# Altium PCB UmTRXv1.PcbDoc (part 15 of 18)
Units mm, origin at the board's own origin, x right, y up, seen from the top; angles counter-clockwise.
Board outline 172 x 113 mm, 6 copper layers (Top Layer, GND, MidLayer1, Mid-Layer 2, InternalPlane2, Bottom Layer); 766 components, 613 nets, 3008 pads, 1360 vias.
Unrouted connection lines stored in the file: 2.
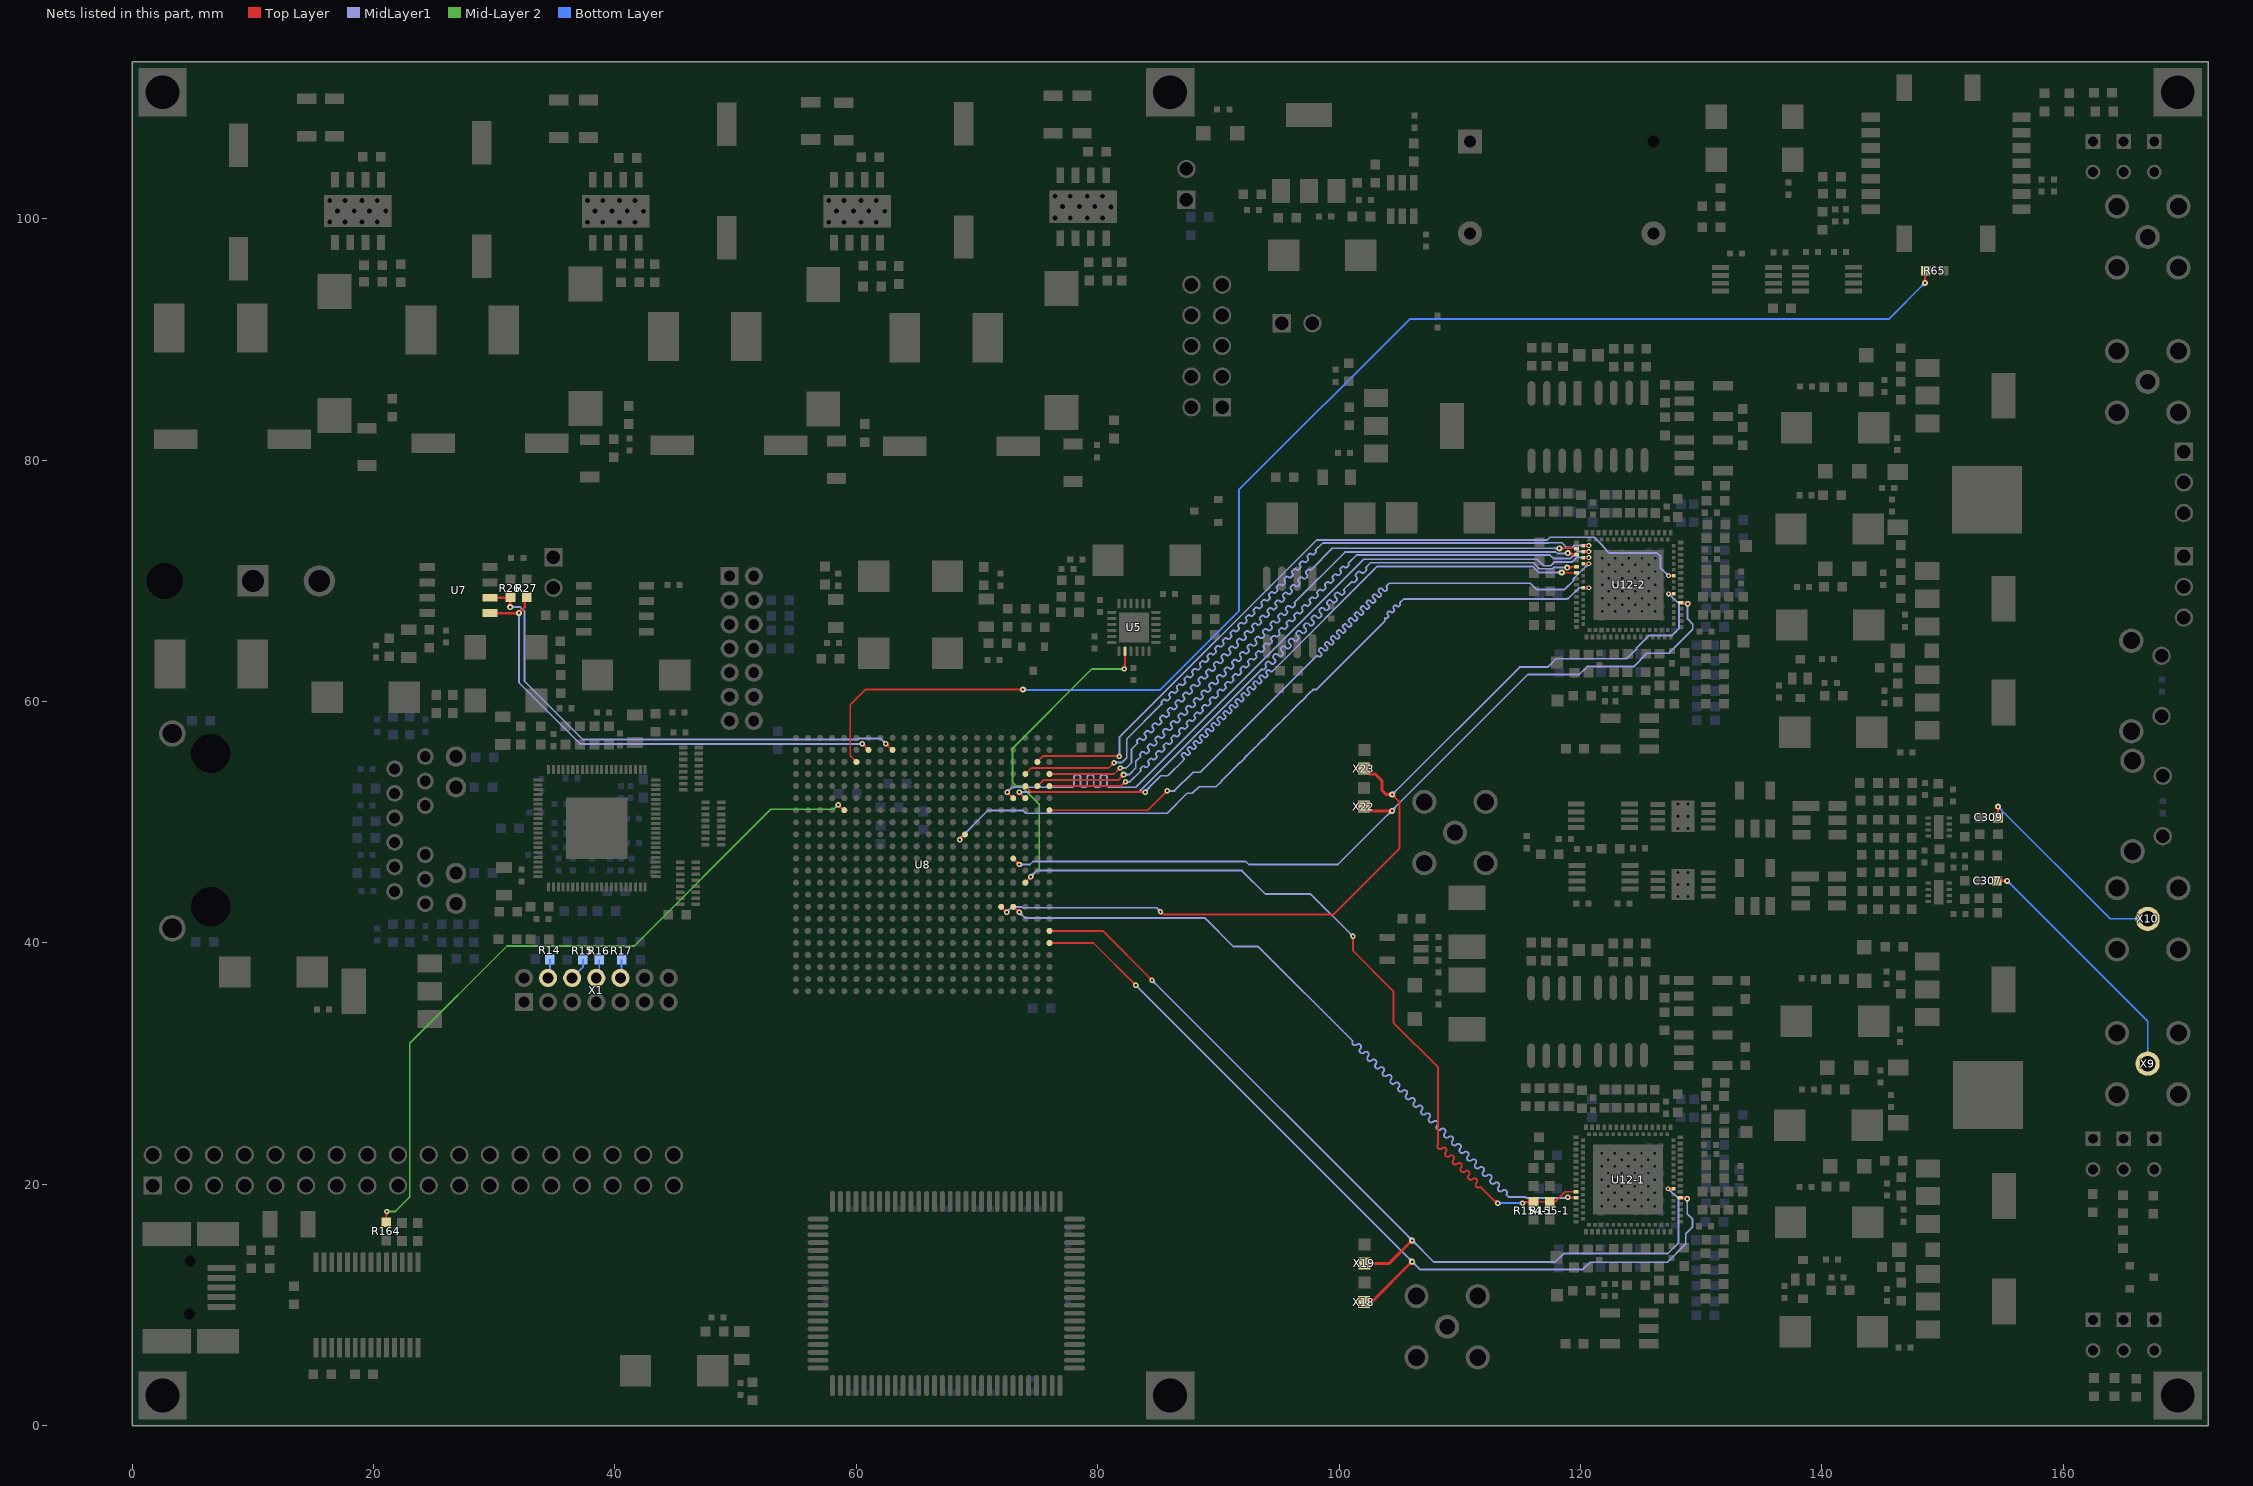
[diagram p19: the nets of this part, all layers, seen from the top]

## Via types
v1: diameter 0.45, hole 0.2, Top Layer to Bottom Layer, tented both sides, 554 vias
v2: diameter 0.5, hole 0.2, Top Layer to Bottom Layer, tented both sides, 468 vias
v3: diameter 0.7, hole 0.3, Top Layer to Bottom Layer, tented both sides, 206 vias
v4: diameter 0.4, hole 0.2, Top Layer to Bottom Layer, tented both sides, 82 vias
v5: diameter 0.8, hole 0.3, Top Layer to Bottom Layer, tented both sides, 16 vias
v6: diameter 0.6, hole 0.25, Top Layer to Bottom Layer, tented both sides, 16 vias
v7: diameter 0.5, hole 0.3, Top Layer to Bottom Layer, tented both sides, 8 vias
v8: diameter 0.7, hole 0.3, Top Layer to Bottom Layer, 4 vias
v9: diameter 0.6, hole 0.3, Top Layer to Bottom Layer, tented both sides, 4 vias
v10: diameter 0.5, hole 0.2, Top Layer to Bottom Layer, 2 vias

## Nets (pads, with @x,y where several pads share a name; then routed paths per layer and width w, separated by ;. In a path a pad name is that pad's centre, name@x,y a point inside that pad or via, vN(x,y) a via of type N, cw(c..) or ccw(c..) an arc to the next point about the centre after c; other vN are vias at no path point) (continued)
RX2D4: U8.V3 U12-2.11 | length 65.1
  Top Layer w0.15: U8.V3@74,53 74.5,52.5 v1(83.95,52.5) ; v1@83.844,52.394 ccw(c83.588,52.138) 83.588,52.5 ccw(c83.588,52.862) v1@83.844,52.606 ; v2(118.45,70.7) 118.475,70.675 119.666,70.675 U12-2.11@119.671,70.68
  MidLayer1 w0.15: v1(83.95,52.5) 83.95,52.566 85.234,53.85 85.8,53.85 87.105,55.155 ccw(c87.006,55.254) 87.105,55.353 86.991,55.467 cw(c87.09,55.566) 86.991,55.665 87.041,55.715 cw(c87.14,55.616) 87.239,55.715 87.353,55.601 ccw(c87.452,55.7) 87.551,55.601 87.6,55.65 ccw(c87.501,55.749) 87.6,55.848 87.486,55.962 cw(c87.585,56.061) 87.486,56.16 87.536,56.21 cw(c87.635,56.111) 87.734,56.21 87.848,56.096 ccw(c87.947,56.195) 88.046,56.096 88.095,56.145 ccw(c87.996,56.244) 88.095,56.343 87.981,56.457 cw(c88.08,56.556) 87.981,56.655 88.031,56.705 cw(c88.13,56.606) 88.229,56.705 88.343,56.591 ccw(c88.442,56.69) 88.541,56.591 88.59,56.64 ccw(c88.491,56.739) 88.59,56.838 88.476,56.952 cw(c88.575,57.051) 88.476,57.15 88.526,57.2 cw(c88.625,57.101) 88.724,57.2 88.838,57.086 ccw(c88.937,57.185) 89.036,57.086 89.085,57.135 ccw(c88.986,57.234) 89.085,57.333 88.971,57.447 cw(c89.07,57.546) 88.971,57.645 89.021,57.695 cw(c89.12,57.596) 89.219,57.695 89.333,57.581 ccw(c89.432,57.68) 89.531,57.581 89.58,57.63 ccw(c89.481,57.729) 89.58,57.828 89.466,57.942 cw(c89.565,58.041) 89.466,58.14 89.516,58.189 cw(c89.615,58.09) 89.714,58.189 89.828,58.076 ccw(c89.927,58.175) 90.026,58.076 90.075,58.125 ccw(c89.976,58.224) 90.075,58.323 89.961,58.437 cw(c90.06,58.536) 89.961,58.635 90.011,58.684 cw(c90.11,58.585) 90.209,58.684 90.322,58.57 ccw(c90.421,58.669) 90.52,58.57 90.57,58.62 ccw(c90.471,58.719) 90.57,58.818 90.456,58.932 cw(c90.555,59.031) 90.456,59.13 90.506,59.179 cw(c90.605,59.08) 90.703,59.179 90.817,59.065 ccw(c90.916,59.164) 91.015,59.065 91.065,59.115 ccw(c90.966,59.214) 91.065,59.313 90.951,59.427 cw(c91.05,59.526) 90.951,59.625 91,59.674 cw(c91.099,59.575) 91.198,59.674 91.312,59.56 ccw(c91.411,59.659) 91.51,59.56 91.56,59.61 ccw(c91.461,59.709) 91.56,59.808 91.446,59.922 cw(c91.545,60.021) 91.446,60.12 91.495,60.169 cw(c91.594,60.07) 91.693,60.169 91.807,60.055 ccw(c91.906,60.154) 92.005,60.055 92.055,60.105 ccw(c91.956,60.204) 92.055,60.303 91.941,60.417 cw(c92.04,60.516) 91.941,60.615 91.99,60.664 cw(c92.089,60.565) 92.188,60.664 92.302,60.55 ccw(c92.401,60.649) 92.5,60.55 92.55,60.6 ccw(c92.451,60.699) 92.55,60.798 92.436,60.912 cw(c92.535,61.011) 92.436,61.11 92.485,61.159 cw(c92.584,61.06) 92.683,61.159 92.797,61.045 ccw(c92.896,61.144) 92.995,61.045 93.045,61.095 ccw(c92.946,61.194) 93.045,61.293 92.931,61.407 cw(c93.03,61.506) 92.931,61.605 92.98,61.654 cw(c93.079,61.555) 93.178,61.654 93.292,61.54 ccw(c93.391,61.639) 93.49,61.54 93.54,61.59 ccw(c93.441,61.689) 93.54,61.788 93.426,61.902 cw(c93.525,62.001) 93.426,62.1 93.475,62.149 cw(c93.574,62.05) 93.673,62.149 93.787,62.035 ccw(c93.886,62.134) 93.985,62.035 94.035,62.085 ccw(c93.936,62.184) 94.035,62.283 93.991,62.327 cw(c94.09,62.426) 93.991,62.525 94.04,62.574 cw(c94.139,62.475) 94.238,62.574 94.282,62.53 ccw(c94.381,62.629) 94.48,62.53 103.15,71.2 116.05,71.2 116.55,70.7 v2(118.45,70.7) ; v1@83.95,52.65 ccw(c83.95,52.854) 84.094,52.71 ; v1@84.1,52.5 cw(c84.621,52.5) 84.253,52.868 ; v2@118.326,70.576 ccw(c118.028,70.278) 118.028,70.7 ccw(c118.028,71.122) v2@118.326,70.824
RX2D5: U8.T1 U12-2.8 | length 64.7
  Top Layer w0.15: U8.T1@76,51 84.15,51 v1(85.75,52.6) ; v1@85.6,52.6 cw(c85.238,52.6) 85.494,52.344 cw(c85.75,52.088) v1@85.75,52.45
  Top Layer w0.2: U12-2.8@120.246,71.43 v4@120.671,71.43 ; v4@120.625,71.359 ccw(c120.455,71.188) 120.455,71.43 ccw(c120.455,71.671) v4@120.625,71.501
  MidLayer1 w0.15: v1(85.75,52.6) 86.353,52.6 87.904,54.15 88.5,54.15 98.106,63.756 cw(c98.184,63.678) 98.262,63.756 ccw(c98.361,63.855) 98.46,63.756 98.509,63.806 ccw(c98.41,63.905) 98.509,64.004 98.432,64.082 98.354,64.159 cw(c98.453,64.258) 98.354,64.357 98.403,64.407 cw(c98.502,64.308) 98.601,64.407 98.757,64.251 ccw(c98.856,64.35) 98.955,64.251 99.004,64.301 ccw(c98.905,64.4) 99.004,64.499 98.849,64.654 cw(c98.948,64.753) 98.849,64.852 98.898,64.902 cw(c98.997,64.803) 99.096,64.902 99.174,64.824 99.252,64.746 ccw(c99.351,64.845) 99.45,64.746 99.499,64.796 ccw(c99.4,64.895) 99.499,64.994 99.421,65.071 99.344,65.149 cw(c99.443,65.248) 99.344,65.347 99.393,65.397 cw(c99.492,65.298) 99.591,65.397 99.669,65.319 99.747,65.241 ccw(c99.846,65.34) 99.945,65.241 99.994,65.291 ccw(c99.895,65.39) 99.994,65.489 99.839,65.644 cw(c99.938,65.743) 99.839,65.842 99.888,65.892 cw(c99.987,65.793) 100.086,65.892 100.164,65.814 100.242,65.736 ccw(c100.341,65.835) 100.44,65.736 100.489,65.786 ccw(c100.39,65.885) 100.489,65.984 100.411,66.061 100.334,66.139 cw(c100.433,66.238) 100.334,66.337 100.383,66.387 cw(c100.482,66.288) 100.581,66.387 100.659,66.309 100.737,66.231 ccw(c100.836,66.33) 100.935,66.231 100.984,66.281 ccw(c100.885,66.38) 100.984,66.479 100.829,66.634 cw(c100.928,66.733) 100.829,66.832 100.878,66.882 cw(c100.977,66.783) 101.076,66.882 101.232,66.726 ccw(c101.331,66.825) 101.43,66.726 101.479,66.776 ccw(c101.38,66.875) 101.479,66.974 101.401,67.051 101.324,67.129 cw(c101.423,67.228) 101.324,67.327 101.373,67.377 cw(c101.472,67.278) 101.571,67.377 101.649,67.299 101.727,67.221 ccw(c101.826,67.32) 101.925,67.221 101.974,67.271 ccw(c101.875,67.37) 101.974,67.469 101.896,67.546 101.819,67.624 cw(c101.918,67.723) 101.819,67.822 101.868,67.872 cw(c101.967,67.773) 102.066,67.872 102.222,67.716 ccw(c102.321,67.815) 102.42,67.716 102.469,67.766 ccw(c102.37,67.865) 102.469,67.964 102.391,68.041 102.314,68.119 cw(c102.413,68.218) 102.314,68.317 102.363,68.367 cw(c102.462,68.268) 102.561,68.367 102.639,68.289 102.717,68.211 ccw(c102.816,68.31) 102.915,68.211 102.964,68.261 ccw(c102.865,68.36) 102.964,68.459 102.886,68.536 102.809,68.614 cw(c102.908,68.713) 102.809,68.812 102.858,68.862 cw(c102.957,68.763) 103.056,68.862 103.134,68.784 103.212,68.706 ccw(c103.311,68.805) 103.41,68.706 103.459,68.756 ccw(c103.36,68.855) 103.459,68.954 103.304,69.109 cw(c103.402,69.208) 103.304,69.307 103.353,69.357 cw(c103.452,69.258) 103.551,69.357 103.629,69.279 103.707,69.201 ccw(c103.806,69.3) 103.905,69.201 103.954,69.25 ccw(c103.855,69.349) 103.954,69.448 cw(c104.032,69.526) 103.954,69.604 104.15,69.8 115.831,69.8 116.331,69.3 118.701,69.3 119.425,70.024 119.425,70.189 120.666,71.43 v4(120.696,71.43) ; v1@85.856,52.494 cw(c86.112,52.238) 86.112,52.6 cw(c86.112,52.962) v1@85.856,52.706 ; 120.431,71.195 cw(c120.696,70.93) v4@120.696,71.305 ; 120.504,71.268 ccw(c120.342,71.43) v4@120.571,71.43
RX2D6: U8.U3 U12-2.9 | length 64.8
  Top Layer w0.15: v1@73.5,52.35 cw(c73.5,51.988) 73.756,52.244 cw(c74.012,52.5) v1@73.65,52.5 ; v1(73.5,52.5) U8.U3@74,52 ; v2(118.9,71.1) 118.85,71.05 118.85,71 119.03,71.18 U12-2.9@119.671,71.18 ; v2@118.918,71.082 cw(c119.153,70.847) 119.153,71.18 ; v2@119.024,70.976 cw(c119.515,70.484) U12-2.9@119.515,71.18
  MidLayer1 w0.15: v1(73.5,52.5) 83.4,52.5 83.55,52.65 83.55,52.666 93.534,62.65 93.75,62.65 93.949,62.849 ccw(c93.899,62.898) 93.949,62.948 cw(c94.076,63.075) 93.949,63.203 94.013,63.266 cw(c94.14,63.139) 94.267,63.266 94.366,63.167 ccw(c94.493,63.294) 94.621,63.167 94.684,63.231 ccw(c94.557,63.358) 94.684,63.485 94.585,63.584 cw(c94.713,63.712) 94.585,63.839 94.649,63.903 cw(c94.776,63.775) 94.904,63.903 94.953,63.853 95.003,63.804 ccw(c95.13,63.931) 95.257,63.804 95.321,63.867 ccw(c95.193,63.994) 95.321,64.122 95.222,64.221 cw(c95.349,64.348) 95.222,64.475 95.285,64.539 cw(c95.413,64.412) 95.54,64.539 95.589,64.489 95.639,64.44 ccw(c95.766,64.567) 95.894,64.44 95.957,64.504 ccw(c95.83,64.631) 95.957,64.758 95.858,64.857 cw(c95.985,64.984) 95.858,65.112 95.922,65.175 cw(c96.049,65.048) 96.176,65.175 96.275,65.076 ccw(c96.403,65.204) 96.53,65.076 96.594,65.14 ccw(c96.466,65.267) 96.594,65.395 96.495,65.494 cw(c96.622,65.621) 96.495,65.748 96.558,65.812 cw(c96.685,65.684) 96.813,65.812 96.912,65.713 ccw(c97.039,65.84) 97.166,65.713 97.23,65.776 ccw(c97.103,65.904) 97.23,66.031 97.18,66.08 97.131,66.13 cw(c97.258,66.257) 97.131,66.384 97.195,66.448 cw(c97.322,66.321) 97.449,66.448 97.548,66.349 ccw(c97.675,66.476) 97.803,66.349 97.866,66.413 ccw(c97.739,66.54) 97.866,66.667 97.817,66.717 97.767,66.766 cw(c97.895,66.894) 97.767,67.021 97.831,67.085 cw(c97.958,66.957) 98.086,67.085 98.185,66.986 ccw(c98.312,67.113) 98.439,66.986 98.503,67.049 ccw(c98.375,67.176) 98.503,67.304 98.404,67.403 cw(c98.531,67.53) 98.404,67.657 98.467,67.721 cw(c98.595,67.594) 98.722,67.721 98.821,67.622 ccw(c98.948,67.749) 99.075,67.622 99.139,67.686 ccw(c99.012,67.813) 99.139,67.94 99.04,68.039 cw(c99.167,68.166) 99.04,68.294 99.104,68.357 cw(c99.231,68.23) 99.358,68.357 99.408,68.308 99.457,68.258 ccw(c99.585,68.386) 99.712,68.258 99.776,68.322 ccw(c99.648,68.449) 99.776,68.577 99.677,68.676 cw(c99.804,68.803) 99.677,68.93 99.74,68.994 cw(c99.867,68.866) 99.995,68.994 100.044,68.944 100.094,68.895 ccw(c100.221,69.022) 100.348,68.895 100.412,68.958 ccw(c100.285,69.086) 100.412,69.213 100.362,69.262 101.039,69.939 ccw(c101.18,70.08) 101.322,69.939 101.428,70.045 ccw(c101.286,70.186) 101.428,70.328 cw(c101.569,70.469) 101.428,70.611 101.534,70.717 cw(c101.675,70.575) 101.817,70.717 ccw(c101.958,70.858) 102.099,70.717 102.206,70.823 ccw(c102.064,70.964) 102.206,71.106 102.6,71.5 116.104,71.5 116.591,71.013 117.684,71.013 117.797,71.125 118.875,71.125 v2(118.9,71.1) ; v1@73.606,52.394 cw(c73.862,52.138) 73.862,52.5 cw(c73.862,52.862) v1@73.606,52.606
RX2D7: U8.U4 U12-2.6 | length 64.9
  Top Layer w0.15: v1@72.5,52.35 cw(c72.5,51.988) 72.756,52.244 cw(c73.012,52.5) v1@72.65,52.5 ; v1(72.5,52.5) U8.U4@73,52
  Top Layer w0.2: U12-2.6@120.246,71.93 v4@120.671,71.93 ; v4@120.625,71.859 ccw(c120.455,71.688) 120.455,71.93 ccw(c120.455,72.171) v4@120.625,72.001
  MidLayer1 w0.15: v1(72.5,52.5) 72.9,52.9 77.805,52.9 ccw(c77.805,53.12) 78.025,53.12 78.025,53.715 cw(c78.245,53.715) 78.245,53.935 78.355,53.935 cw(c78.355,53.715) 78.575,53.715 78.575,53.12 ccw(c78.795,53.12) 78.795,52.9 78.905,52.9 ccw(c78.905,53.12) 79.125,53.12 79.125,53.715 cw(c79.345,53.715) 79.345,53.935 79.455,53.935 cw(c79.455,53.715) 79.675,53.715 79.675,53.12 ccw(c79.895,53.12) 79.895,52.9 80.005,52.9 ccw(c80.005,53.12) 80.225,53.12 80.225,53.715 cw(c80.445,53.715) 80.445,53.935 80.555,53.935 cw(c80.555,53.715) 80.775,53.715 80.775,53.12 ccw(c80.995,53.12) 80.995,52.9 83.15,52.9 102.05,71.8 116.413,71.8 116.95,71.263 117.534,71.263 117.834,71.563 119.285,71.563 119.652,71.93 v4(120.696,71.93) ; v1@72.5,52.65 ccw(c72.5,53.012) 72.756,52.756 ccw(c73.012,52.5) v1@72.65,52.5 ; v4@120.608,71.841 ccw(c120.394,71.628) 120.394,71.93 ccw(c120.394,72.232) v4@120.608,72.018
RX2D8: U8.V2 U12-2.5 | length 66
  Top Layer w0.15: U8.V2@75,53 75.5,53.5 81.7,53.5 v2(82.15,53.95) ; v2@81.975,53.95 cw(c81.553,53.95) 81.851,53.651 cw(c82.15,53.353) v2@82.15,53.775 ; v2(118.95,72.3) 118.95,72.25 119.02,72.18 U12-2.5@119.671,72.18 ; v2@118.968,72.318 ccw(c119.3,72.65) 119.3,72.18 ; v2@119.074,72.424 ccw(c119.662,73.012) U12-2.5@119.662,72.18
  MidLayer1 w0.15: v2(82.15,53.95) 82.6,53.95 83.15,54.5 83.15,55.05 83.545,55.445 ccw(c83.531,55.459) 83.545,55.473 cw(c83.672,55.601) 83.545,55.728 83.609,55.791 cw(c83.736,55.664) 83.863,55.791 83.877,55.777 83.891,55.763 ccw(c84.019,55.89) 84.146,55.763 84.21,55.827 ccw(c84.082,55.954) 84.21,56.081 84.195,56.095 84.181,56.11 cw(c84.309,56.237) 84.181,56.364 84.245,56.428 cw(c84.372,56.301) 84.5,56.428 84.514,56.414 84.528,56.4 ccw(c84.655,56.527) 84.782,56.4 84.846,56.463 ccw(c84.719,56.59) 84.846,56.718 84.832,56.732 84.818,56.746 cw(c84.945,56.873) 84.818,57.001 84.881,57.064 cw(c85.009,56.937) 85.136,57.064 85.15,57.05 85.164,57.036 ccw(c85.292,57.163) 85.419,57.036 85.482,57.1 ccw(c85.355,57.227) 85.482,57.354 85.468,57.368 85.454,57.382 cw(c85.581,57.51) 85.454,57.637 85.518,57.701 cw(c85.645,57.573) 85.772,57.701 85.786,57.686 85.801,57.672 ccw(c85.928,57.8) 86.055,57.672 86.119,57.736 ccw(c85.992,57.863) 86.119,57.991 86.105,58.005 86.091,58.019 cw(c86.218,58.146) 86.091,58.273 86.154,58.337 cw(c86.281,58.21) 86.409,58.337 86.423,58.323 86.437,58.309 ccw(c86.564,58.436) 86.692,58.309 86.755,58.372 ccw(c86.628,58.5) 86.755,58.627 86.741,58.641 86.727,58.655 cw(c86.854,58.782) 86.727,58.91 86.791,58.973 cw(c86.918,58.846) 87.045,58.973 87.059,58.959 87.073,58.945 ccw(c87.201,59.072) 87.328,58.945 87.392,59.009 ccw(c87.264,59.136) 87.392,59.263 87.377,59.277 87.363,59.292 cw(c87.491,59.419) 87.363,59.546 87.427,59.61 cw(c87.554,59.483) 87.682,59.61 87.696,59.596 87.71,59.582 ccw(c87.837,59.709) 87.964,59.582 88.028,59.645 ccw(c87.901,59.772) 88.028,59.9 88.014,59.914 88,59.928 cw(c88.127,60.055) 88,60.183 88.063,60.246 cw(c88.191,60.119) 88.318,60.246 88.332,60.232 88.346,60.218 ccw(c88.473,60.345) 88.601,60.218 88.664,60.282 ccw(c88.537,60.409) 88.664,60.536 88.65,60.55 88.636,60.564 cw(c88.763,60.692) 88.636,60.819 88.7,60.883 cw(c88.827,60.755) 88.954,60.883 88.968,60.868 88.983,60.854 ccw(c89.11,60.982) 89.237,60.854 89.301,60.918 ccw(c89.174,61.045) 89.301,61.173 89.287,61.187 89.273,61.201 cw(c89.4,61.328) 89.273,61.455 89.336,61.519 cw(c89.463,61.392) 89.591,61.519 89.605,61.505 89.619,61.491 ccw(c89.746,61.618) 89.874,61.491 89.937,61.554 ccw(c89.81,61.682) 89.937,61.809 89.923,61.823 89.909,61.837 cw(c90.036,61.964) 89.909,62.092 89.973,62.155 cw(c90.1,62.028) 90.227,62.155 90.241,62.141 90.255,62.127 ccw(c90.383,62.254) 90.51,62.127 90.574,62.191 ccw(c90.446,62.318) 90.574,62.445 90.559,62.459 90.545,62.474 cw(c90.673,62.601) 90.545,62.728 90.609,62.792 cw(c90.736,62.665) 90.863,62.792 90.878,62.778 90.892,62.763 ccw(c91.019,62.891) 91.146,62.763 91.21,62.827 ccw(c91.083,62.954) 91.21,63.082 91.196,63.096 91.182,63.11 cw(c91.309,63.237) 91.182,63.365 91.245,63.428 cw(c91.373,63.301) 91.5,63.428 91.514,63.414 91.528,63.4 ccw(c91.655,63.527) 91.783,63.4 91.846,63.464 ccw(c91.719,63.591) 91.846,63.718 91.832,63.732 91.818,63.746 cw(c91.945,63.874) 91.818,64.001 91.882,64.065 cw(c92.009,63.937) 92.136,64.065 92.15,64.05 92.165,64.036 ccw(c92.292,64.164) 92.419,64.036 92.483,64.1 ccw(c92.355,64.227) 92.483,64.354 92.454,64.383 cw(c92.582,64.51) 92.454,64.637 92.518,64.701 cw(c92.645,64.574) 92.773,64.701 92.787,64.687 92.801,64.673 ccw(c92.928,64.8) 93.056,64.673 93.119,64.736 ccw(c92.992,64.864) 93.119,64.991 93.105,65.005 93.091,65.019 cw(c93.218,65.146) 93.091,65.274 93.155,65.337 cw(c93.282,65.21) 93.409,65.337 93.423,65.323 93.437,65.309 ccw(c93.565,65.436) 93.692,65.309 93.756,65.373 ccw(c93.628,65.5) 93.756,65.627 93.741,65.641 93.727,65.656 cw(c93.855,65.783) 93.727,65.91 93.791,65.974 cw(c93.918,65.846) 94.045,65.974 94.06,65.96 94.074,65.945 ccw(c94.201,66.073) 94.328,65.945 94.392,66.009 ccw(c94.265,66.136) 94.392,66.264 94.378,66.278 94.364,66.292 cw(c94.491,66.419) 94.364,66.547 94.427,66.61 cw(c94.555,66.483) 94.682,66.61 94.71,66.582 ccw(c94.837,66.709) 94.965,66.582 95.028,66.646 ccw(c94.901,66.773) 95.028,66.9 95.014,66.914 95,66.928 cw(c95.127,67.056) 95,67.183 95.064,67.247 cw(c95.191,67.119) 95.318,67.247 95.332,67.232 95.347,67.218 ccw(c95.474,67.346) 95.601,67.218 95.665,67.282 ccw(c95.537,67.409) 95.665,67.536 95.651,67.551 95.636,67.565 cw(c95.764,67.692) 95.636,67.819 95.7,67.883 cw(c95.827,67.756) 95.955,67.883 95.969,67.869 95.983,67.855 ccw(c96.11,67.982) 96.238,67.855 96.301,67.918 ccw(c96.174,68.046) 96.301,68.173 cw(c96.315,68.187) 96.301,68.201 100.5,72.4 117.949,72.4 118.074,72.275 118.925,72.275 v2(118.95,72.3) ; v2@82.274,53.826 cw(c82.572,53.528) 82.572,53.95 cw(c82.572,54.372) v2@82.274,54.074 ; 118.467,72.275 ccw(c118.467,72.783) v2@118.826,72.424 ; 118.588,72.275 cw(c118.588,71.938) v2@118.826,72.176
RX2D9: U8.V1 U12-2.4 | length 64.7
  Top Layer w0.15: U8.V1@76,53 81.9,53 82.3,53.4 v1(82.3,53.35) ; 81.958,53.058 cw(c82.3,52.717) v1@82.3,53.2 ; 82.079,53.179 ccw(c81.909,53.35) v1@82.15,53.35
  Top Layer w0.2: U12-2.4@120.246,72.43 v4@120.671,72.43 ; v4@120.625,72.359 ccw(c120.455,72.188) 120.455,72.43 ccw(c120.455,72.671) v4@120.625,72.501
  MidLayer1 w0.15: v1(82.3,53.35) 82.65,53.35 ; v1@82.409,53.247 cw(c82.65,53.017) 82.65,53.35 ; v1@82.409,53.453 ccw(c82.65,53.683) 82.65,53.35 ; v4@120.608,72.341 ccw(c120.394,72.128) 120.394,72.43 ccw(c120.394,72.732) v4@120.608,72.518 ; v4(120.696,72.43) 119.752,72.43 119.185,71.863 117.751,71.863 117.464,72.15 101.45,72.15 100.767,71.467 cw(c100.661,71.361) 100.767,71.255 100.661,71.149 cw(c100.555,71.255) 100.449,71.149 ccw(c100.342,71.042) 100.236,71.149 100.13,71.042 ccw(c100.236,70.936) 100.13,70.83 cw(c100.024,70.724) 100.13,70.618 100.024,70.512 cw(c99.918,70.618) 99.812,70.512 ccw(c99.706,70.406) 99.6,70.512 99.494,70.406 ccw(c99.6,70.3) 99.494,70.194 cw(c99.388,70.088) 99.494,69.982 99.388,69.876 cw(c99.282,69.982) 99.176,69.876 ccw(c99.07,69.77) 98.964,69.876 98.858,69.77 ccw(c98.964,69.664) 98.858,69.558 cw(c98.752,69.452) 98.858,69.345 98.752,69.239 cw(c98.645,69.345) 98.539,69.239 ccw(c98.433,69.133) 98.327,69.239 98.221,69.133 ccw(c98.327,69.027) 98.221,68.921 cw(c98.115,68.815) 98.221,68.709 98.115,68.603 cw(c98.009,68.709) 97.903,68.603 ccw(c97.797,68.497) 97.691,68.603 97.585,68.497 ccw(c97.691,68.391) 97.585,68.285 cw(c97.479,68.179) 97.585,68.073 97.479,67.967 cw(c97.373,68.073) 97.267,67.967 ccw(c97.161,67.861) 97.054,67.967 96.948,67.861 ccw(c97.054,67.754) 96.948,67.648 cw(c96.842,67.542) 96.948,67.436 96.842,67.33 cw(c96.736,67.436) 96.63,67.33 ccw(c96.524,67.224) 96.418,67.33 96.312,67.224 ccw(c96.418,67.118) 96.312,67.012 cw(c96.206,66.906) 96.312,66.8 96.206,66.694 cw(c96.1,66.8) 95.994,66.694 ccw(c95.888,66.588) 95.782,66.694 95.676,66.588 ccw(c95.782,66.482) 95.676,66.376 cw(c95.57,66.27) 95.676,66.163 95.57,66.057 cw(c95.463,66.163) 95.357,66.057 ccw(c95.251,65.951) 95.145,66.057 95.039,65.951 ccw(c95.145,65.845) 95.039,65.739 cw(c94.933,65.633) 95.039,65.527 94.933,65.421 cw(c94.827,65.527) 94.721,65.421 ccw(c94.615,65.315) 94.509,65.421 94.403,65.315 ccw(c94.509,65.209) 94.403,65.103 cw(c94.297,64.997) 94.403,64.891 94.297,64.785 cw(c94.191,64.891) 94.085,64.785 ccw(c93.979,64.679) 93.872,64.785 93.766,64.679 ccw(c93.872,64.572) 93.766,64.466 cw(c93.66,64.36) 93.766,64.254 93.66,64.148 cw(c93.554,64.254) 93.448,64.148 ccw(c93.342,64.042) 93.236,64.148 93.13,64.042 ccw(c93.236,63.936) 93.13,63.83 cw(c93.024,63.724) 93.13,63.618 93.024,63.512 cw(c92.918,63.618) 92.812,63.512 ccw(c92.706,63.406) 92.6,63.512 92.494,63.406 ccw(c92.6,63.3) 92.494,63.194 cw(c92.388,63.088) 92.494,62.981 92.388,62.875 cw(c92.281,62.981) 92.175,62.875 ccw(c92.069,62.769) 91.963,62.875 91.857,62.769 ccw(c91.963,62.663) 91.857,62.557 cw(c91.751,62.451) 91.857,62.345 91.751,62.239 cw(c91.645,62.345) 91.539,62.239 ccw(c91.433,62.133) 91.327,62.239 91.221,62.133 ccw(c91.327,62.027) 91.221,61.921 cw(c91.115,61.815) 91.221,61.709 91.115,61.603 cw(c91.009,61.709) 90.903,61.603 ccw(c90.797,61.497) 90.691,61.603 90.584,61.497 ccw(c90.691,61.391) 90.584,61.284 cw(c90.478,61.178) 90.584,61.072 90.478,60.966 cw(c90.372,61.072) 90.266,60.966 ccw(c90.16,60.86) 90.054,60.966 89.948,60.86 ccw(c90.054,60.754) 89.948,60.648 cw(c89.842,60.542) 89.948,60.436 89.842,60.33 cw(c89.736,60.436) 89.63,60.33 ccw(c89.524,60.224) 89.418,60.33 89.312,60.224 ccw(c89.418,60.118) 89.312,60.012 cw(c89.206,59.906) 89.312,59.8 89.206,59.693 cw(c89.1,59.8) 88.993,59.693 ccw(c88.887,59.587) 88.781,59.693 88.675,59.587 ccw(c88.781,59.481) 88.675,59.375 cw(c88.569,59.269) 88.675,59.163 88.569,59.057 cw(c88.463,59.163) 88.357,59.057 ccw(c88.251,58.951) 88.145,59.057 88.039,58.951 ccw(c88.145,58.845) 88.039,58.739 cw(c87.933,58.633) 88.039,58.527 87.933,58.421 cw(c87.827,58.527) 87.721,58.421 ccw(c87.615,58.315) 87.509,58.421 87.402,58.315 ccw(c87.509,58.209) 87.402,58.102 cw(c87.296,57.996) 87.402,57.89 87.296,57.784 cw(c87.19,57.89) 87.084,57.784 ccw(c86.978,57.678) 86.872,57.784 86.766,57.678 ccw(c86.872,57.572) 86.766,57.466 cw(c86.66,57.36) 86.766,57.254 86.66,57.148 cw(c86.554,57.254) 86.448,57.148 ccw(c86.342,57.042) 86.236,57.148 86.13,57.042 ccw(c86.236,56.936) 86.13,56.83 cw(c86.024,56.724) 86.13,56.618 86.024,56.511 cw(c85.918,56.618) 85.811,56.511 ccw(c85.705,56.405) 85.599,56.511 85.493,56.405 ccw(c85.599,56.299) 85.493,56.193 cw(c85.387,56.087) 85.493,55.981 85.387,55.875 cw(c85.281,55.981) 85.175,55.875 ccw(c85.069,55.769) 84.963,55.875 84.857,55.769 ccw(c84.963,55.663) 84.857,55.557 cw(c84.751,55.451) 84.857,55.345 84.751,55.239 cw(c84.645,55.345) 84.539,55.239 ccw(c84.433,55.133) 84.327,55.239 84.22,55.133 ccw(c84.327,55.027) 84.22,54.92 cw(c84.114,54.814) 84.22,54.708 84.114,54.602 cw(c84.008,54.708) 83.902,54.602 ccw(c83.796,54.496) 83.69,54.602 83.584,54.496 ccw(c83.69,54.39) 83.584,54.284 82.65,53.35
RX2D10: U8.W1 U12-2.3 | length 65.6
  Top Layer w0.15: U8.W1@76,54 81.35,54 v1(81.85,54.5) ; v1@81.7,54.5 cw(c81.338,54.5) 81.594,54.244 cw(c81.85,53.988) v1@81.85,54.35 ; v2(118.25,72.7) 118.749,72.7 118.774,72.725 119.626,72.725 U12-2.3@119.671,72.68 ; v2@118.374,72.576 cw(c118.672,72.278) 118.672,72.7 cw(c118.672,73.122) v2@118.374,72.824
  MidLayer1 w0.15: v1(81.85,54.5) 82.35,54.5 82.8,54.95 82.8,56.05 83.295,56.545 ccw(c83.281,56.559) 83.295,56.573 cw(c83.422,56.701) 83.295,56.828 83.359,56.891 cw(c83.486,56.764) 83.613,56.891 83.627,56.877 83.641,56.863 ccw(c83.769,56.99) 83.896,56.863 83.96,56.927 ccw(c83.832,57.054) 83.96,57.181 83.945,57.195 83.931,57.21 cw(c84.059,57.337) 83.931,57.464 83.995,57.528 cw(c84.122,57.401) 84.25,57.528 84.264,57.514 84.278,57.5 ccw(c84.405,57.627) 84.532,57.5 84.596,57.563 ccw(c84.469,57.69) 84.596,57.818 84.582,57.832 84.568,57.846 cw(c84.695,57.973) 84.568,58.101 84.631,58.164 cw(c84.759,58.037) 84.886,58.164 84.9,58.15 84.914,58.136 ccw(c85.042,58.263) 85.169,58.136 85.232,58.2 ccw(c85.105,58.327) 85.232,58.454 85.218,58.468 85.204,58.482 cw(c85.331,58.61) 85.204,58.737 85.268,58.801 cw(c85.395,58.673) 85.522,58.801 85.536,58.786 85.551,58.772 ccw(c85.678,58.9) 85.805,58.772 85.869,58.836 ccw(c85.742,58.963) 85.869,59.091 85.855,59.105 85.841,59.119 cw(c85.968,59.246) 85.841,59.373 85.904,59.437 cw(c86.031,59.31) 86.159,59.437 86.173,59.423 86.187,59.409 ccw(c86.314,59.536) 86.442,59.409 86.505,59.472 ccw(c86.378,59.6) 86.505,59.727 86.491,59.741 86.477,59.755 cw(c86.604,59.882) 86.477,60.01 86.541,60.073 cw(c86.668,59.946) 86.795,60.073 86.809,60.059 86.823,60.045 ccw(c86.951,60.172) 87.078,60.045 87.142,60.109 ccw(c87.014,60.236) 87.142,60.363 87.127,60.377 87.113,60.392 cw(c87.241,60.519) 87.113,60.646 87.177,60.71 cw(c87.304,60.583) 87.432,60.71 87.446,60.696 87.46,60.682 ccw(c87.587,60.809) 87.714,60.682 87.778,60.745 ccw(c87.651,60.872) 87.778,61 87.764,61.014 87.75,61.028 cw(c87.877,61.155) 87.75,61.283 87.813,61.346 cw(c87.941,61.219) 88.068,61.346 88.082,61.332 88.096,61.318 ccw(c88.223,61.445) 88.351,61.318 88.414,61.382 ccw(c88.287,61.509) 88.414,61.636 88.4,61.65 88.386,61.664 cw(c88.513,61.792) 88.386,61.919 88.45,61.983 cw(c88.577,61.855) 88.704,61.983 88.718,61.968 88.733,61.954 ccw(c88.86,62.082) 88.987,61.954 89.051,62.018 ccw(c88.924,62.145) 89.051,62.273 89.037,62.287 89.023,62.301 cw(c89.15,62.428) 89.023,62.555 89.086,62.619 cw(c89.213,62.492) 89.341,62.619 89.355,62.605 89.369,62.591 ccw(c89.496,62.718) 89.624,62.591 89.687,62.654 ccw(c89.56,62.782) 89.687,62.909 89.673,62.923 89.659,62.937 cw(c89.786,63.064) 89.659,63.192 ; v1@81.956,54.394 cw(c82.212,54.138) 82.212,54.5 cw(c82.212,54.862) v1@81.956,54.606 ; 89.659,63.192 89.723,63.255 cw(c89.85,63.128) 89.977,63.255 89.991,63.241 90.005,63.227 ccw(c90.133,63.354) 90.26,63.227 90.324,63.291 ccw(c90.196,63.418) 90.324,63.545 90.309,63.559 90.295,63.574 cw(c90.423,63.701) 90.295,63.828 90.359,63.892 cw(c90.486,63.765) 90.613,63.892 90.628,63.878 90.642,63.863 ccw(c90.769,63.991) 90.896,63.863 90.96,63.927 ccw(c90.833,64.054) 90.96,64.182 90.946,64.196 90.932,64.21 cw(c91.059,64.337) 90.932,64.465 90.995,64.528 cw(c91.123,64.401) 91.25,64.528 91.264,64.514 91.278,64.5 ccw(c91.405,64.627) 91.533,64.5 91.596,64.564 ccw(c91.469,64.691) 91.596,64.818 91.582,64.832 91.568,64.846 cw(c91.695,64.974) 91.568,65.101 91.632,65.165 cw(c91.759,65.037) 91.886,65.165 91.9,65.15 91.915,65.136 ccw(c92.042,65.264) 92.169,65.136 92.233,65.2 ccw(c92.105,65.327) 92.233,65.454 92.204,65.483 cw(c92.332,65.61) 92.204,65.737 92.268,65.801 cw(c92.395,65.674) 92.523,65.801 92.537,65.787 92.551,65.773 ccw(c92.678,65.9) 92.806,65.773 92.869,65.836 ccw(c92.742,65.964) 92.869,66.091 92.855,66.105 92.841,66.119 cw(c92.968,66.246) 92.841,66.374 92.905,66.437 cw(c93.032,66.31) 93.159,66.437 93.173,66.423 93.187,66.409 ccw(c93.315,66.536) 93.442,66.409 93.506,66.473 ccw(c93.378,66.6) 93.506,66.727 93.491,66.741 93.477,66.756 cw(c93.605,66.883) 93.477,67.01 93.541,67.074 cw(c93.668,66.946) 93.795,67.074 93.81,67.06 93.824,67.045 ccw(c93.951,67.173) 94.078,67.045 94.142,67.109 ccw(c94.015,67.236) 94.142,67.364 94.128,67.378 94.114,67.392 cw(c94.241,67.519) 94.114,67.647 94.177,67.71 cw(c94.305,67.583) 94.432,67.71 94.46,67.682 ccw(c94.587,67.809) 94.715,67.682 94.778,67.746 ccw(c94.651,67.873) 94.778,68 94.764,68.014 94.75,68.028 cw(c94.877,68.156) 94.75,68.283 94.814,68.347 cw(c94.941,68.219) 95.068,68.347 95.082,68.332 95.097,68.318 ccw(c95.224,68.446) 95.351,68.318 95.415,68.382 ccw(c95.287,68.509) 95.415,68.636 95.401,68.651 95.386,68.665 cw(c95.514,68.792) 95.386,68.919 95.45,68.983 cw(c95.577,68.856) 95.705,68.983 95.719,68.969 95.733,68.955 ccw(c95.86,69.082) 95.987,68.955 96.051,69.018 ccw(c95.924,69.146) 96.051,69.273 96.037,69.287 96.023,69.301 cw(c96.15,69.428) 96.023,69.556 96.086,69.619 cw(c96.214,69.492) 96.341,69.619 96.355,69.605 96.369,69.591 ccw(c96.497,69.718) 96.624,69.591 96.688,69.655 ccw(c96.56,69.782) 96.688,69.909 96.659,69.938 cw(c96.787,70.065) 96.659,70.192 96.723,70.256 cw(c96.85,70.128) 96.977,70.256 96.992,70.242 97.006,70.227 ccw(c97.133,70.355) 97.26,70.227 97.324,70.291 ccw(c97.197,70.418) 97.324,70.546 97.31,70.56 97.296,70.574 cw(c97.423,70.701) 97.296,70.828 97.359,70.892 cw(c97.487,70.765) 97.614,70.892 ccw(c97.628,70.906) 97.642,70.892 99.45,72.7 v2(118.25,72.7) ; v2@118.126,72.576 ccw(c117.828,72.278) 117.828,72.7 ccw(c117.828,73.122) v2@118.126,72.824
RX2D11: U8.W3 U12-2.2 | length 65
  Top Layer w0.15: U8.W3@74,54 74.5,54.5 80.9,54.5 v1(81.35,54.95) ; v1@81.2,54.95 cw(c80.838,54.95) 81.094,54.694 cw(c81.35,54.438) v1@81.35,54.8
  Top Layer w0.2: U12-2.2@120.246,72.93 v4@120.671,72.93 ; v4@120.625,72.859 ccw(c120.455,72.688) 120.455,72.93 ccw(c120.455,73.171) v4@120.625,73.001
  MidLayer1 w0.15: v1(81.35,54.95) 82,54.95 82.4,55.35 82.4,56.9 85.313,59.813 cw(c85.419,59.919) 85.313,60.025 85.419,60.131 cw(c85.525,60.025) 85.631,60.131 ccw(c85.737,60.237) 85.843,60.131 85.949,60.237 ccw(c85.843,60.343) 85.949,60.449 cw(c86.055,60.555) 85.949,60.662 86.055,60.768 cw(c86.162,60.662) 86.268,60.768 ccw(c86.374,60.874) 86.48,60.768 86.586,60.874 ccw(c86.48,60.98) 86.586,61.086 cw(c86.692,61.192) 86.586,61.298 86.692,61.404 cw(c86.798,61.298) 86.904,61.404 ccw(c87.01,61.51) 87.116,61.404 87.222,61.51 ccw(c87.116,61.616) 87.222,61.722 cw(c87.328,61.828) 87.222,61.934 87.328,62.04 cw(c87.434,61.934) 87.54,62.04 ccw(c87.646,62.146) 87.753,62.04 87.859,62.146 ccw(c87.753,62.253) 87.859,62.359 cw(c87.965,62.465) 87.859,62.571 87.965,62.677 cw(c88.071,62.571) 88.177,62.677 ccw(c88.283,62.783) 88.389,62.677 88.495,62.783 ccw(c88.389,62.889) 88.495,62.995 cw(c88.601,63.101) 88.495,63.207 88.601,63.313 cw(c88.707,63.207) 88.813,63.313 ccw(c88.919,63.419) 89.025,63.313 89.131,63.419 ccw(c89.025,63.525) 89.131,63.631 cw(c89.237,63.737) 89.131,63.844 89.237,63.95 cw(c89.344,63.844) 89.45,63.95 ccw(c89.556,64.056) 89.662,63.95 89.768,64.056 ccw(c89.662,64.162) 89.768,64.268 cw(c89.874,64.374) 89.768,64.48 89.874,64.586 cw(c89.98,64.48) 90.086,64.586 ccw(c90.192,64.692) 90.298,64.586 90.404,64.692 ccw(c90.298,64.798) 90.404,64.904 cw(c90.51,65.01) 90.404,65.116 90.51,65.222 cw(c90.616,65.116) 90.722,65.222 ccw(c90.828,65.328) 90.934,65.222 91.041,65.328 ccw(c90.934,65.434) 91.041,65.541 cw(c91.147,65.647) 91.041,65.753 91.147,65.859 cw(c91.253,65.753) 91.359,65.859 ccw(c91.465,65.965) 91.571,65.859 91.677,65.965 ccw(c91.571,66.071) 91.677,66.177 cw(c91.783,66.283) 91.677,66.389 91.783,66.495 cw(c91.889,66.389) 91.995,66.495 ccw(c92.101,66.601) 92.207,66.495 92.313,66.601 ccw(c92.207,66.707) 92.313,66.813 cw(c92.419,66.919) 92.313,67.025 92.419,67.132 cw(c92.525,67.025) 92.632,67.132 ccw(c92.738,67.238) 92.844,67.132 92.95,67.238 ccw(c92.844,67.344) 92.95,67.45 cw(c93.056,67.556) 92.95,67.662 93.056,67.768 cw(c93.162,67.662) 93.268,67.768 ccw(c93.374,67.874) 93.48,67.768 93.586,67.874 ccw(c93.48,67.98) 93.586,68.086 cw(c93.692,68.192) 93.586,68.298 93.692,68.404 cw(c93.798,68.298) 93.904,68.404 ccw(c94.01,68.51) 94.116,68.404 94.223,68.51 ccw(c94.116,68.616) 94.223,68.723 cw(c94.329,68.829) 94.223,68.935 94.329,69.041 cw(c94.435,68.935) 94.541,69.041 ccw(c94.647,69.147) 94.753,69.041 94.859,69.147 ccw(c94.753,69.253) 94.859,69.359 cw(c94.965,69.465) 94.859,69.571 94.965,69.677 cw(c95.071,69.571) 95.177,69.677 ccw(c95.283,69.783) 95.389,69.677 95.495,69.783 ccw(c95.389,69.889) 95.495,69.995 cw(c95.601,70.101) 95.495,70.207 95.601,70.314 cw(c95.707,70.207) 95.814,70.314 ccw(c95.92,70.42) 96.026,70.314 96.132,70.42 ccw(c96.026,70.526) 96.132,70.632 cw(c96.238,70.738) 96.132,70.844 96.238,70.95 cw(c96.344,70.844) 96.45,70.95 ccw(c96.556,71.056) 96.662,70.95 96.768,71.056 ccw(c96.662,71.162) 96.768,71.268 cw(c96.874,71.374) 96.768,71.48 96.874,71.586 cw(c96.98,71.48) 97.086,71.586 ccw(c97.192,71.692) 97.298,71.586 97.405,71.692 ccw(c97.298,71.798) 97.405,71.905 cw(c97.511,72.011) 97.405,72.117 97.511,72.223 cw(c97.617,72.117) 97.723,72.223 ccw(c97.829,72.329) 97.935,72.223 98.041,72.329 ccw(c97.935,72.435) 98.041,72.541 98.642,73.142 117.35,73.142 117.372,73.163 118.471,73.163 118.838,72.796 119.335,72.796 119.468,72.93 v4(120.696,72.93) ; v1@81.456,54.844 cw(c81.712,54.588) 81.712,54.95 cw(c81.712,55.312) v1@81.456,55.056 ; v4@120.608,72.841 ccw(c120.394,72.628) 120.394,72.93 ccw(c120.394,73.232) v4@120.608,73.018
RX2EN: U8.Y2 U12-2.76 | length 65.3
  Top Layer w0.15: U8.Y2@75,55 75.5,55.5 81.75,55.5 v1(81.8,55.45) ; 81.317,55.5 cw(c81.317,54.967) v1@81.694,55.344 ; 81.559,55.5 ccw(c81.559,55.691) v1@81.694,55.556
  Top Layer w0.2: v4@127.321,70.43 U12-2.76@127.746,70.43 ; v4@127.367,70.359 cw(c127.537,70.188) 127.537,70.43 cw(c127.537,70.671) v4@127.367,70.501
  MidLayer1 w0.15: v1@81.694,55.556 ccw(c81.438,55.812) 81.8,55.812 ccw(c82.162,55.812) v1@81.906,55.556 ; v1(81.8,55.45) 81.8,57.05 98.142,73.392 117.247,73.392 117.477,73.623 121.134,73.623 121.871,72.885 121.871,72.825 122.387,72.308 126.369,72.308 126.621,72.056 126.621,71.105 v4(127.296,70.43) ; v4@127.171,70.43 ccw(c126.869,70.43) 127.083,70.643 ccw(c127.296,70.857) v4@127.296,70.555
RX2IQSEL: U8.P8 U12-2.16 | length 65.5
  Top Layer w0.15: v1(68.55,48.55) U8.P8@69,49 ; v1@68.55,48.725 ccw(c68.55,49.147) 68.849,48.849 ccw(c69.147,48.55) v1@68.725,48.55
  Top Layer w0.2: U12-2.16@120.246,69.43 v4@120.671,69.43 ; v4@120.625,69.359 ccw(c120.455,69.188) 120.455,69.43 ccw(c120.455,69.671) v4@120.625,69.501
  MidLayer1 w0.15: v1(68.55,48.55) 68.55,48.636 70.889,50.975 73.825,50.975 74.049,50.751 85.751,50.751 87.4,52.4 87.85,52.4 88.4,52.95 89.8,52.95 90.261,53.411 90.261,53.422 90.332,53.492 90.332,53.51 90.427,53.604 90.444,53.604 90.515,53.675 90.525,53.675 90.898,54.048 90.898,54.058 90.968,54.129 90.968,54.146 90.984,54.162 91.063,54.241 91.08,54.241 91.151,54.312 91.162,54.312 91.534,54.684 91.534,54.694 91.605,54.765 91.605,54.782 91.7,54.877 91.717,54.877 91.788,54.948 91.798,54.948 92.17,55.32 92.17,55.331 92.241,55.402 92.241,55.419 92.32,55.498 92.336,55.514 92.353,55.514 92.424,55.584 92.434,55.584 92.807,55.957 92.807,55.967 92.878,56.038 92.878,56.055 92.972,56.15 92.99,56.15 93.06,56.221 93.071,56.221 93.443,56.593 93.443,56.604 93.514,56.674 93.514,56.692 93.609,56.786 93.626,56.786 93.697,56.857 93.707,56.857 94.079,57.229 94.079,57.24 94.15,57.311 94.15,57.328 94.245,57.423 94.262,57.423 94.333,57.494 94.344,57.494 94.716,57.866 94.716,57.876 94.787,57.947 94.787,57.964 94.882,58.059 94.899,58.059 94.97,58.13 94.98,58.13 95.352,58.502 95.352,58.513 95.423,58.584 95.423,58.601 95.439,58.616 95.518,58.696 95.535,58.696 95.606,58.766 95.616,58.766 95.989,59.139 95.989,59.149 96.059,59.22 96.059,59.237 96.154,59.332 96.172,59.332 96.242,59.403 96.253,59.403 96.625,59.775 96.625,59.786 96.696,59.856 96.696,59.874 96.775,59.953 96.791,59.968 96.808,59.968 96.879,60.039 96.889,60.039 97.261,60.411 97.261,60.422 97.332,60.493 97.332,60.51 97.427,60.605 97.444,60.605 97.515,60.676 97.526,60.676 97.85,61 98.116,61 103.789,66.673 103.789,66.939 103.796,66.932 ccw(c103.895,67.031) 103.994,66.932 104.043,66.981 ccw(c103.944,67.08) 104.043,67.179 104.036,67.186 104.029,67.193 cw(c104.128,67.292) 104.029,67.391 104.079,67.441 cw(c104.178,67.342) 104.277,67.441 104.284,67.434 104.291,67.427 ccw(c104.39,67.526) 104.489,67.427 104.538,67.476 ccw(c104.439,67.575) 104.538,67.674 104.531,67.681 104.524,67.688 cw(c104.623,67.787) 104.524,67.886 104.574,67.936 cw(c104.673,67.837) 104.772,67.936 104.779,67.929 104.786,67.922 ccw(c104.885,68.021) 104.984,67.922 105.033,67.971 ccw(c104.934,68.07) 105.033,68.169 105.026,68.176 105.35,68.5 115.323,68.5 118.884,68.5 118.934,68.55 119.012,68.55 119.892,69.43 v4(120.696,69.43) ; v1@68.55,48.725 ccw(c68.55,48.941) 68.702,48.788 ; v1@68.725,48.55 cw(c69.354,48.55) 68.909,48.995 ; v4@120.608,69.341 ccw(c120.394,69.128) 120.394,69.43 ccw(c120.394,69.732) v4@120.608,69.518
RXD1: R164.1 U8.T18 | length 62.9
  Top Layer w0.15: v1@20.994,17.644 cw(c20.859,17.509) 21.05,17.509 ; R164.1@21.05,16.85 21.05,17.8 21.1,17.85 v1(21.1,17.75) ; 21.05,17.267 cw(c21.583,17.267) v1@21.206,17.644 ; v1@58.5,51.3 cw(c58.5,50.938) 58.756,51.194 cw(c59.012,51.45) v1@58.65,51.45 ; v1(58.5,51.45) U8.T18@58.95,51
  Mid-Layer 2 w0.15: v1(21.1,17.75) 21.8,17.75 23,18.95 23,31.7 31.05,39.75 41.596,39.75 52.921,51.075 58.125,51.075 v1(58.5,51.45) ; v1@21.206,17.644 cw(c21.462,17.388) 21.462,17.75 cw(c21.462,18.112) v1@21.206,17.856 ; v1@58.35,51.45 cw(c57.988,51.45) 58.244,51.194 cw(c58.5,50.938) v1@58.5,51.3
RXD2: R65.1 U8.Y17 | length 118
  Top Layer w0.15: U8.Y17@60,55 59.5,55.5 59.5,59.75 60.75,61 v2(73.8,61) ; v2@73.676,60.876 ccw(c73.378,60.578) 73.378,61 ccw(c73.378,61.422) v2@73.676,61.124 ; v2@148.426,94.824 ccw(c148.128,95.122) 148.55,95.122 ccw(c148.972,95.122) v2@148.674,94.824 ; v2(148.55,94.7) R65.1@148.55,95.6
  Bottom Layer w0.15: v2(73.8,61) 73.8,60.95 85.15,60.95 91.7,67.5 91.7,77.55 105.85,91.7 145.55,91.7 v2(148.55,94.7) ; v2@73.924,60.876 cw(c74.102,60.698) 74.102,60.95 ; v2@73.924,61.124 ccw(c74.343,61.543) 74.343,60.95 ; v2@148.375,94.7 cw(c147.953,94.7) 148.251,94.401 cw(c148.55,94.103) v2@148.55,94.525
RXIN1: C307.2 X9.1 | length 22.1
  Top Layer w0.2: C307.2@154.5,45.15 v2(155.35,45.15) ; v2@155.244,45.044 ccw(c154.988,44.788) 154.988,45.15 ccw(c154.988,45.512) v2@155.244,45.256
  Bottom Layer w0.15: v2@155.35,44.975 cw(c155.35,44.553) 155.649,44.851 cw(c155.947,45.15) v2@155.525,45.15 ; v2(155.35,45.15) 167,33.5 X9.1@167,30
RXIN2: C309.2 X10.1 | length 18.4
  Top Layer w0.2: v2@154.494,51.194 cw(c154.238,50.938) 154.6,50.938 cw(c154.962,50.938) v2@154.706,51.194 ; C309.2@154.6,50.4 v2(154.6,51.3)
  Bottom Layer w0.15: v2@154.6,51.125 cw(c154.6,50.703) 154.899,51.001 cw(c155.197,51.3) v2@154.775,51.3 ; v2(154.6,51.3) 163.9,42 X10.1@167,42
SCL: R26.2 U7.6 U8.AA14 | length 45
  Top Layer w0.15: v1@62.45,56.35 cw(c62.45,55.988) 62.706,56.244 cw(c62.962,56.5) v1@62.6,56.5 ; v1(62.45,56.5) 62.95,56 U8.AA14@63,56
  Top Layer w0.2: U7.6@29.647,68.607 31.301,68.607 R26.2@31.34,68.646 31.34,67.861 v2(31.314,67.835) ; v2@31.208,67.941 ccw(c30.89,68.259) R26.2@31.34,68.259 ; 31.34,68.136 ccw(c31.615,68.136) v2@31.42,67.941
  MidLayer1 w0.15: v2(31.314,67.835) 32.165,67.835 32.5,67.5 32.5,61.7 37.35,56.85 60.1,56.85 60.2,56.95 62,56.95 v1(62.45,56.5) ; v2@31.438,67.712 cw(c31.737,67.413) 31.737,67.835 cw(c31.737,68.258) v2@31.438,67.959 ; v1@62.3,56.5 ccw(c61.938,56.5) 62.194,56.756 ccw(c62.45,57.012) v1@62.45,56.65
SCLK1: U8.F1 U12-1.70 X19.1 | length 78
  Top Layer w0.15: U8.F1@76,41 80.4,41 v1(84.5,36.9) ; v1@84.35,36.9 ccw(c83.988,36.9) 84.244,37.156 ccw(c84.5,37.412) v1@84.5,37.05
  Top Layer w0.2: v4@127.282,19.638 U12-1.70@127.707,19.638 ; v4@127.328,19.567 cw(c127.498,19.397) 127.498,19.638 cw(c127.498,19.879) v4@127.328,19.709
  Top Layer w0.25: X19.1@102.1,13.45 104.15,13.45 v2(106.05,15.35) ; v2@105.925,15.35 cw(c105.623,15.35) 105.837,15.137 cw(c106.05,14.923) v2@106.05,15.225
  MidLayer1 w0.15: v1@84.5,36.75 cw(c84.5,36.388) 84.756,36.644 cw(c85.012,36.9) v1@84.65,36.9 ; v1(84.5,36.9) v2(106.05,15.35) 107.836,13.564 117.914,13.564 118.608,14.258 127.215,14.258 128.132,15.175 128.132,18.793 127.287,19.638 v4(127.257,19.638) ; v2@105.875,15.35 ccw(c105.453,15.35) 105.751,15.649 ccw(c106.05,15.947) v2@106.05,15.525 ; v2@106.05,15.175 cw(c106.05,14.753) 106.349,15.051 cw(c106.647,15.35) v2@106.225,15.35 ; v4@127.257,19.513 cw(c127.257,19.138) 127.522,19.403 ; v4@127.382,19.638 ccw(c127.611,19.638) 127.449,19.476
SCLK2: U8.H5 U12-2.70 X23.1 | length 82.4
  Top Layer w0.15: U8.H5@72,43 v1(72.45,42.55) ; v1@72.3,42.55 ccw(c71.938,42.55) 72.194,42.806 ccw(c72.45,43.062) v1@72.45,42.7 ; v1(85.2,42.6) 85.45,42.35 ; v1@85.203,42.45 cw(c85.208,42.108) 85.45,42.35 ; v1@85.35,42.597 ccw(c85.692,42.592) 85.45,42.35 ; v2@104.4,52.125 cw(c104.4,51.703) 104.699,52.001 cw(c104.997,52.3) v2@104.575,52.3 ; v2(104.4,52.3) 105,51.7 105,47.825 99.525,42.35 85.45,42.35
  Top Layer w0.2: v4@127.321,68.93 U12-2.70@127.746,68.93 ; v4@127.367,68.859 cw(c127.537,68.688) 127.537,68.93 cw(c127.537,69.171) v4@127.367,69.001
  Top Layer w0.25: X23.1@102.05,54.45 102.5,54 103,54 103.55,53.45 103.55,52.65 103.9,52.3 v2(104.4,52.3) ; v2@104.312,52.212 ccw(c104.098,51.998) 104.098,52.3 ccw(c104.098,52.602) v2@104.312,52.388
  MidLayer1 w0.15: v1(72.45,42.55) 72.875,42.975 73.676,42.975 73.726,42.925 83.974,42.925 84.875,42.925 v1(85.2,42.6) ; v1@72.45,42.7 ccw(c72.45,43.062) 72.706,42.806 ccw(c72.962,42.55) v1@72.6,42.55 ; v1@85.05,42.6 ccw(c84.688,42.6) 84.944,42.856 ccw(c85.2,43.112) v1@85.2,42.75 ; v2(104.4,52.3) 114.956,62.856 117.282,62.856 117.975,63.548 119.383,63.548 119.384,63.55 119.716,63.55 119.717,63.548 123.821,63.548 124.65,64.377 124.65,64.466 125.651,65.467 127.57,65.467 128.171,66.067 128.171,68.085 127.326,68.93 v4(127.296,68.93) ; v2@104.4,52.475 ccw(c104.4,52.897) 104.699,52.599 ccw(c104.997,52.3) v2@104.575,52.3 ; v4@127.296,68.805 cw(c127.296,68.43) 127.561,68.695 ; v4@127.421,68.93 ccw(c127.65,68.93) 127.488,68.768
SDA: R27.2 U7.5 U8.AA16 | length 43.8
  Top Layer w0.15: v1@60.5,56.35 cw(c60.5,55.988) 60.756,56.244 cw(c61.012,56.5) v1@60.65,56.5 ; v1(60.5,56.5) U8.AA16@61,56
  Top Layer w0.2: U7.5@29.647,67.337 32.031,67.337 v2(32.044,67.349) 32.517,67.822 R27.2@32.517,68.62 ; 31.651,67.337 ccw(c31.651,67.742) v2@31.938,67.456 ; 31.712,67.337 cw(c31.712,67.017) v2@31.938,67.243 ; v2@32.044,67.499 ccw(c32.044,67.862) 32.3,67.606 ccw(c32.556,67.349) v2@32.194,67.349
  MidLayer1 w0.15: v2@31.92,67.226 cw(c31.621,66.927) 32.044,66.927 cw(c32.466,66.927) v2@32.167,67.226 ; v2@32.044,67.3 32.044,61.556 37.1,56.5 v1(60.5,56.5) ; v1@60.394,56.394 ccw(c60.138,56.138) 60.138,56.5 ccw(c60.138,56.862) v1@60.394,56.606
SEN1: U8.E1 U12-1.67 X18.1 | length 79
  Top Layer w0.15: U8.E1@76,40 79.65,40 v1(83.15,36.5) ; v1@83,36.5 ccw(c82.638,36.5) 82.894,36.756 ccw(c83.15,37.012) v1@83.15,36.65
  Top Layer w0.2: U12-1.67@128.282,18.888 v1@128.959,18.888 ; U12-1.67@128.378,18.888 cw(c128.378,18.358) v1@128.753,18.733
  Top Layer w0.25: X18.1@102.049,10.25 102.7,10.25 v2(106.05,13.6) ; v2@105.925,13.6 cw(c105.623,13.6) 105.837,13.387 cw(c106.05,13.173) v2@106.05,13.475
  MidLayer1 w0.15: v1@83.15,36.35 cw(c83.15,35.988) 83.406,36.244 cw(c83.662,36.5) v1@83.3,36.5 ; v1(83.15,36.5) 106.695,12.955 120.2,12.955 120.795,13.55 127.214,13.55 128.732,15.068 128.732,15.91 129.272,16.45 129.272,17.133 128.841,17.564 v1(128.841,18.821) ; v2@105.875,13.6 ccw(c105.453,13.6) 105.751,13.899 ccw(c106.05,14.197) v2@106.05,13.775 ; v2@106.05,13.425 cw(c106.05,13.003) 106.349,13.301 cw(c106.647,13.6) v2@106.225,13.6 ; v1@128.735,18.715 cw(c128.479,18.459) 128.841,18.459 cw(c129.204,18.459) v1@128.948,18.715
SEN2: U8.M4 U12-2.67 X22.1 | length 74.4
  Top Layer w0.15: U8.M4@73,47 v1(73.5,46.5) ; v1@73.325,46.5 ccw(c72.903,46.5) 73.201,46.799 ccw(c73.5,47.097) v1@73.5,46.675
  Top Layer w0.2: U12-2.67@128.321,68.18 v1@128.998,68.18 ; U12-2.67@128.417,68.18 cw(c128.417,67.65) v1@128.792,68.025
  Top Layer w0.25: X22.1@102.05,51.3 102.3,51.3 102.65,50.95 v2(104.4,50.95) ; v2@104.312,50.862 ccw(c104.098,50.648) 104.098,50.95 ccw(c104.098,51.252) v2@104.312,51.038
  MidLayer1 w0.15: v1(73.5,46.5) 74.389,46.5 74.639,46.75 92.261,46.75 92.511,46.5 99.9,46.5 115.646,62.246 119.893,62.246 120.551,62.905 124.405,62.905 125.5,64 127.305,64 129.311,66.007 129.311,66.424 128.88,66.855 v1(128.88,68.113) ; v1@73.624,46.376 cw(c73.922,46.078) 73.922,46.5 cw(c73.922,46.922) v1@73.624,46.624 ; 104.016,50.616 cw(c104.4,50.232) v2@104.4,50.775 ; 104.137,50.737 ccw(c103.923,50.95) v2@104.225,50.95 ; v2@104.4,51.125 ccw(c104.4,51.427) 104.613,51.213 ; v2@104.575,50.95 cw(c105.118,50.95) 104.734,51.334 ; v1@128.774,68.007 cw(c128.518,67.751) 128.88,67.751 cw(c129.243,67.751) v1@128.986,68.007
TCK: R15.1 X1.6 | length 1.9
  Bottom Layer w0.15: X1.6@36.45,37.1 37.341,37.991 R15.1@37.341,38.62
TDI: R17.1 X1.10 | length 1.5
  Bottom Layer w0.15: X1.10@40.45,37.1 40.55,37.2 R17.1@40.55,38.6
TDO: R16.1 X1.8 | length 1.6
  Bottom Layer w0.15: X1.8@38.45,37.1 38.7,37.35 R16.1@38.7,38.6
TMS: R14.1 X1.4 | length 1.6
  Bottom Layer w0.15: X1.4@34.45,37.1 34.604,37.254 R14.1@34.604,38.633
TX1CLK: R154-1.2 R155-1.2 U5.14 U8.K3 U12-1.19 | length 98.8
  Top Layer w0.15: U8.K3@74,45 74.45,45.45 v1(74.45,45.5) ; U8.K3@74.159,45.159 ccw(c73.817,45.5) v1@74.3,45.5 ; 74.279,45.279 cw(c74.45,45.109) v1@74.45,45.35 ; v1@82.094,62.806 ccw(c81.717,63.183) 82.25,63.183 ; v1(82.2,62.7) 82.25,62.75 U5.14@82.25,64.175 ; 82.25,62.941 ccw(c82.441,62.941) v1@82.306,62.806 ; v1@101.044,40.444 cw(c100.788,40.188) 101.15,40.188 cw(c101.512,40.188) v1@101.256,40.444 ; v1(101.15,40.55) 101.15,39.35 104.5,36 104.5,33.4 108.2,29.7 108.2,23.3 ccw(c108.359,23.141) 108.518,22.982 cw(c108.677,22.823) 108.836,22.664 ccw(c108.995,22.505) 109.154,22.346 cw(c109.314,22.186) 109.473,22.027 ccw(c109.632,21.868) 109.791,21.709 cw(c109.95,21.55) 110.109,21.391 ccw(c110.268,21.232) 110.427,21.073 cw(c110.586,20.914) 110.745,20.755 ccw(c110.905,20.595) 111.064,20.436 cw(c111.223,20.277) 111.382,20.118 ccw(c111.541,19.959) 111.7,19.8 113.1,18.4 v1(113.15,18.45) ; 112.723,18.777 ccw(c113.15,19.204) v1@113.15,18.6 ; v1@115.306,18.344 cw(c115.823,17.827) R154-1.2@115.823,18.558 ; 115.461,18.558 ccw(c115.461,18.189) v1(115.2,18.45) 115.308,18.558 R154-1.2@116.111,18.558 R155-1.2@117.461,18.558 117.908,18.558 118.738,19.388 U12-1.19@119.632,19.388
  Mid-Layer 2 w0.15: v1(74.45,45.5) 75.15,46.2 75.15,51.5 73.65,53 73.25,53 72.95,53.3 72.95,56.15 79.5,62.7 v1(82.2,62.7) ; v1@74.45,45.65 ccw(c74.45,46.012) 74.706,45.756 ccw(c74.962,45.5) v1@74.6,45.5 ; v1@82.094,62.594 ccw(c81.838,62.338) 81.838,62.7 ccw(c81.838,63.062) v1@82.094,62.806
  MidLayer1 w0.15: v1(74.45,45.5) 74.95,46 91.95,46 93.9,44.05 97.65,44.05 v1(101.15,40.55) ; v1@74.45,45.65 ccw(c74.45,46.012) 74.706,45.756 ccw(c74.962,45.5) v1@74.6,45.5 ; v1@101,40.55 ccw(c100.638,40.55) 100.894,40.806 ccw(c101.15,41.062) v1@101.15,40.7
  Bottom Layer w0.15: v1(113.15,18.45) 115.15,18.45 115.2,18.4 v1(115.2,18.45) ; v1@113.256,18.344 cw(c113.512,18.088) 113.512,18.45 cw(c113.512,18.812) v1@113.256,18.556 ; v1@115.094,18.344 ccw(c114.838,18.088) 114.838,18.45 ccw(c114.838,18.812) v1@115.094,18.556
TX1D0: U8.H4 U12-1.21 | length 69.2
  Top Layer w0.15: U8.H4@73,43 U8.H4@73.05,43 ; 73.237,42.763 cw(c73.023,42.55) v1@73.325,42.55 ; v1@73.487,42.725 cw(c73.456,43.156) 73.15,42.85 v1@73.5,42.5 ; v1(118.961,18.92) 118.961,18.908 118.961,18.858 118.991,18.888 U12-1.21@119.632,18.888 ; v1@119.067,18.814 cw(c119.246,18.636) 119.246,18.888 ; v1@119.067,19.026 ccw(c119.401,19.36) 119.401,18.888
  MidLayer1 w0.15: v1@73.4,42.65 73.975,42.075 74.676,42.075 88.875,42.075 91.25,39.7 93.3,39.7 101.122,31.878 ccw(c101.317,31.754) 101.44,31.56 cw(c101.599,31.401) 101.758,31.241 ccw(c101.918,31.082) 102.077,30.923 cw(c102.236,30.764) 102.395,30.605 ccw(c102.554,30.446) 102.713,30.287 cw(c102.872,30.128) 103.031,29.969 ccw(c103.19,29.81) 103.349,29.651 cw(c103.509,29.491) 103.668,29.332 ccw(c103.827,29.173) 103.986,29.014 cw(c104.145,28.855) 104.304,28.696 ccw(c104.463,28.537) 104.622,28.378 cw(c104.781,28.219) 104.94,28.06 ccw(c105.1,27.9) 105.259,27.741 cw(c105.418,27.582) 105.577,27.423 ccw(c105.736,27.264) 105.895,27.105 cw(c106.054,26.946) 106.213,26.787 ccw(c106.372,26.628) 106.531,26.469 cw(c106.691,26.309) 106.85,26.15 ccw(c107.009,25.991) 107.168,25.832 cw(c107.327,25.673) 107.486,25.514 ccw(c107.645,25.355) 107.804,25.196 cw(c107.963,25.037) 108.122,24.878 ccw(c108.282,24.718) 108.441,24.559 cw(c108.6,24.4) 108.759,24.241 ccw(c108.918,24.082) 109.077,23.923 cw(c109.236,23.764) 109.395,23.605 ccw(c109.554,23.446) 109.713,23.287 cw(c109.873,23.127) 110.032,22.968 ccw(c110.191,22.809) 110.35,22.65 cw(c110.509,22.491) 110.668,22.332 ccw(c110.827,22.173) 110.986,22.014 cw(c111.145,21.855) 111.304,21.696 ccw(c111.464,21.536) 111.623,21.377 cw(c111.782,21.218) 111.941,21.059 ccw(c112.1,20.9) 112.259,20.741 cw(c112.418,20.582) 112.577,20.423 ccw(c112.736,20.264) 112.895,20.105 cw(c113.055,19.945) 113.214,19.786 ccw(c113.373,19.627) 113.532,19.468 cw(c113.691,19.309) 113.85,19.15 114.042,18.958 115.427,18.958 115.527,18.858 118.961,18.858 v1(118.961,18.92) ; v1@73.5,42.375 cw(c73.5,41.953) 73.799,42.251 cw(c74.097,42.55) v1@73.675,42.55 ; 118.449,18.858 ccw(c118.449,19.432) v1@118.855,19.026
  other v1: 73.5,42.55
